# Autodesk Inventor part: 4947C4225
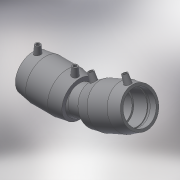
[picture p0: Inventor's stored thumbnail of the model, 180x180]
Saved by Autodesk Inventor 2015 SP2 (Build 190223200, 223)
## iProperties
Created: 2017-06
Part Number: 4947C4225
Material: Generic
Description: PLASSON ADJUSTABLE ELBOW 225
Document SubType Name: Modeling
Designer: KIM
Mass: 55.0731 g
Surface Area: 148.067 cm^2
Volume: 55.0731 cm^3
Density: 1 g/cm^3
Appearance: Default
Author: KIM
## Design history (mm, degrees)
derived "4947C4.ipt"
feature "Solid1::4947C4.ipt"
tag "TaggingFeature1"
body "Solid1"
other parameters: "d2" = 282, "d3" = 105, "d4" = 52.5, "d5" = 253.8, "d7" = 225, "d8" = 168 deg, "d10" = 42, "d11" = 14, "d29" = 141, "d30" = 15, "d31" = 96, "d34" = 5 deg, "d41" = 4, "d42" = 14, "d43" = 0, "d48" = 202.5, "d49" = 24 deg, "d51" = 78 deg, "d52" = 90 deg, "d55" = 67.5, "d57" = 168 deg, "d58" = 13.5, "d60" = 75.56196, "d62" = 3, "d63" = 0, "d_" = 225, "L_1" = 105, "D_" = 282, "A_" = 141, "d_2" = 12, "L_0" = 148, "d54" = 135, "d59" = 251.87321
